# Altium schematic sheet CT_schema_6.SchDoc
size 221 x 258 mm
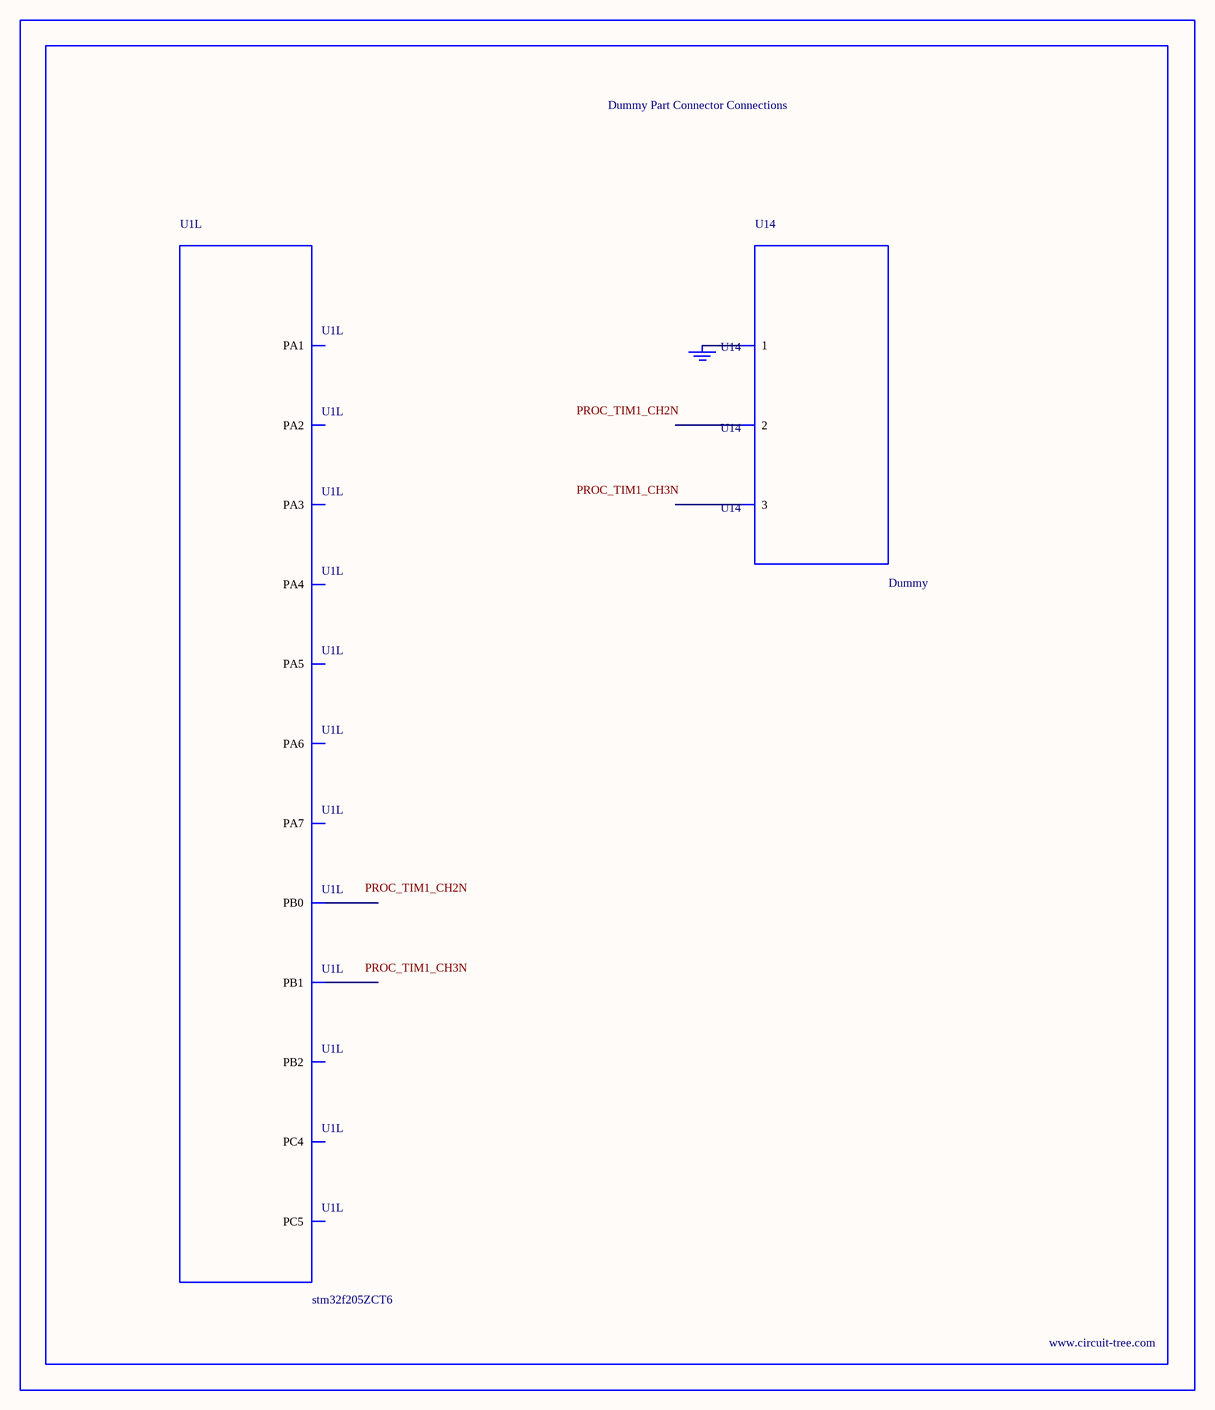
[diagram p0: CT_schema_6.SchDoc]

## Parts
BORDER5  (no value)
GND_INSTANCE_5_0  (no value)
U1  stm32f205ZCT6  [LQFP144]  (part L of 12)
U14  Dummy  [DUMMY_PACKAGE_180]

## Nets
NetGND_INSTANCE_5_0_0: GND_INSTANCE_5_0.0(GND) U14.1

Not connected (* = marked no-connect by the designer): U1 35(PA1) 36(PA2) 37(PA3) 40(PA4) 41(PA5) 42(PA6) 43(PA7) 44(PC4) 45(PC5) 46(PB0) 47(PB1) 48(PB2); U14 2 3

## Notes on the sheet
- Labels drawn without touching a wire or pin: PROC_TIM1_CH2N, PROC_TIM1_CH3N

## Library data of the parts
BORDER5 = BORDER_PAGE5
GND_INSTANCE_5_0 = GND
